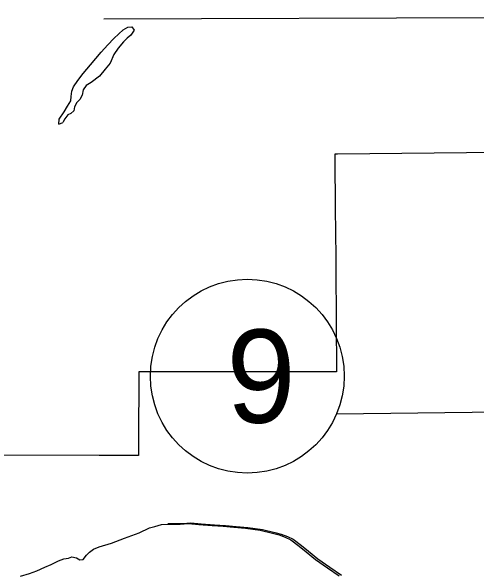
# Model space of a CAD drawing. Extents: x 1127717 to 1741049, y 2026793 to 2244711.
# Drawn here: x 1244598 to 1246182, y 2127719 to 2129633 of the extents above; entities that cross this region are included whole.
import ezdxf

# ---------------------------------------------------------------- set-up
doc = ezdxf.new("R2010")
doc.units = 0
for name, color, linetype in [('27', 7, 'Continuous'), ('5', 7, 'Continuous'), ('6', 7, 'Continuous'), ('9', 7, 'Continuous')]:
    doc.layers.add(name, color=color, linetype=linetype)

msp = doc.modelspace()

# ---------------------------------------------------------------- linework, layer by layer
at = {"layer": '27'}
msp.add_circle((1245401.2, 2128391.4), 330, dxfattribs=at)
at = {"layer": '5'}
for points in [[(1244913.3, 2129607.7), (1246241.2, 2129611.8), (1247614, 2129633.3)], [(1245705.4, 2128263.4), (1246259.1, 2128270.2)]]:
    msp.add_lwpolyline(points, dxfattribs=at)
at = {"layer": '6'}
for points in [[(1246367, 2129154.1), (1245708.7, 2129147.4), (1245705.9, 2129147.4), (1245703.5, 2129147.4), (1245702.6, 2129147.4), (1245699.7, 2129147.3), (1245699.7, 2129141.8), (1245699.8, 2129136.7), (1245699.8, 2129124.2)], [(1245699.8, 2129124.2), (1245700.9, 2128968.7), (1245701.6, 2128873.5), (1245702.1, 2128802.7), (1245702.4, 2128755), (1245704.8, 2128406.6), (1245703.2, 2128406.6), (1245701.4, 2128406.6), (1245699.6, 2128406.6), (1245031.9, 2128406), (1245030.9, 2128164.1), (1245030.9, 2128161.7), (1245030.9, 2128159.6), (1245030.8, 2128121.3), (1244937.6, 2128121.4), (1244897.2, 2128121.4), (1244431.5, 2128122)]]:
    msp.add_lwpolyline(points, dxfattribs=at)
at = {"layer": '9'}
for points in [[(1244760, 2129249.3), (1244761, 2129265.9), (1244778.2, 2129291.4), (1244788.7, 2129310.2), (1244800.1, 2129328.1), (1244801.7, 2129343.7), (1244803.7, 2129360.8), (1244809.2, 2129375.9), (1244824.6, 2129397.4), (1244842.4, 2129421.5), (1244867, 2129451.2), (1244885.3, 2129472.3), (1244904.2, 2129493.9), (1244925.9, 2129518.5), (1244946.3, 2129540.2), (1244963.3, 2129556.2), (1244978.8, 2129570.2), (1244994, 2129579.6), (1245008, 2129580.5), (1245016.3, 2129568.7), (1245004.3, 2129552.4), (1244992.6, 2129541.5), (1244979.5, 2129529.1), (1244961.7, 2129508.1), (1244946.8, 2129486.6), (1244934.7, 2129457.2), (1244917.8, 2129436.7), (1244898, 2129412.6), (1244869.2, 2129391.2), (1244853, 2129380.7), (1244842.5, 2129366.4), (1244839.5, 2129347.8), (1244830.9, 2129333.5), (1244820.8, 2129322.7), (1244812.7, 2129308.4), (1244810.1, 2129294.8), (1244800.9, 2129285.6), (1244790, 2129281.2), (1244779.9, 2129266.9), (1244773.3, 2129255.2)], [(1244760, 2129249.3), (1244773.3, 2129255.2)], [(1245130.4, 2127889.7), (1245146.1, 2127890.4), (1245181.1, 2127890.4), (1245209, 2127891.8), (1245244.5, 2127888.8), (1245289.5, 2127885.6), (1245326.5, 2127883.6), (1245363.1, 2127880.2), (1245402.6, 2127876.8), (1245453.2, 2127869.3), (1245495, 2127859), (1245517.1, 2127853.6), (1245538.3, 2127845.7), (1245557, 2127836.8), (1245585.6, 2127814.5), (1245609.6, 2127796.2), (1245641.3, 2127770.1), (1245682.1, 2127741.2), (1245722.3, 2127713.8)], [(1244628.7, 2127711.1), (1244659.5, 2127719.5), (1244685.1, 2127728.8), (1244711.7, 2127741.5), (1244733.9, 2127750.7), (1244758, 2127762.4), (1244776.8, 2127770), (1244792.2, 2127772.4), (1244804.1, 2127776.8), (1244819.6, 2127772.7), (1244830.8, 2127766), (1244842.3, 2127767.4), (1244853.3, 2127781.7), (1244864, 2127792.5), (1244877.7, 2127803), (1244896.4, 2127810.5), (1244939, 2127823.3), (1244983.4, 2127839.6), (1245033.3, 2127858.6), (1245068.3, 2127875.1), (1245086.1, 2127880.1), (1245109.4, 2127886.8), (1245138.3, 2127888.1), (1245173.2, 2127888.2), (1245201.1, 2127889.5), (1245236.7, 2127886.5), (1245281.7, 2127883.3), (1245318.7, 2127881.4), (1245355.2, 2127877.9), (1245394.7, 2127874.6), (1245445.4, 2127867), (1245487.1, 2127856.7), (1245509.2, 2127851.3), (1245530.4, 2127843.4), (1245549.2, 2127834.5), (1245577.8, 2127812.3), (1245601.7, 2127793.9), (1245633.4, 2127767.8), (1245674.2, 2127738.9), (1245714.4, 2127711.6)]]:
    msp.add_lwpolyline(points, dxfattribs=at)

# ---------------------------------------------------------------- texts
at = {"layer": '27'}
msp.add_text('9', height=316.8, dxfattribs=at).set_placement((1245330.4, 2128233))

doc.saveas('drawing.dxf')
